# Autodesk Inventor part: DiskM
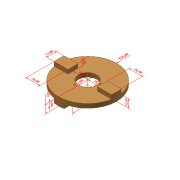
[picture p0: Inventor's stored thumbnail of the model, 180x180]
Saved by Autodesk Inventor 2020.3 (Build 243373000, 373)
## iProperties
Created: 2013-08
Part Number: DiskM
Document SubType Name: Modeling
Designer: hunter love
Density: 1 g/cm^3
Mass: 21.3803 g
Surface Area: 95.2224 cm^2
Volume: 21.3803 cm^3
Material: Generico
Appearance: Orange (Pale)
Author: hunter love
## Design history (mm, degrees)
node "Annotazioni"
  node "Quota radiale 1" dims "d9" = 90 deg, "d17" = 18, "d18" = 18, "d20" = 35 (derived)
  node "Quota diametro 1" dims "d9" = 90 deg, "d17" = 18, "d18" = 18, "d22" = 22 (derived)
  node "Quota lineare 1" dims "d9" = 90 deg, "d17" = 18, "d18" = 18, "d25" = 16.48188 (derived)
  node "Quota lineare 2" dims "d9" = 90 deg, "d17" = 18, "d18" = 18, "d28" = 12 (derived)
  node "Quota lineare 3" dims "d9" = 90 deg, "d17" = 18, "d18" = 18, "d31" = 16.48188 (derived)
  node "Quota lineare 4" dims "d9" = 90 deg, "d17" = 18, "d18" = 18, "d32" = 5 (derived)
  node "Quota lineare 5" dims "d9" = 90 deg, "d17" = 18, "d18" = 18, "d35" = 5 (derived)
  node "Quota lineare 7" dims "d9" = 90 deg, "d17" = 18, "d18" = 18, "d40" = 18 (derived)
  node "Quota lineare 8" dims "d9" = 90 deg, "d17" = 18, "d18" = 18, "d41" = 10 (derived)
  node "Quota lineare 9" dims "d9" = 90 deg, "d17" = 18, "d18" = 18, "d42" = 10 (derived)
  node "Quota lineare 10" dims "d9" = 90 deg, "d17" = 18, "d18" = 18, "d45" = 18 (derived)
  node "Quota lineare 11" dims "d9" = 90 deg, "d17" = 18, "d18" = 18, "d48" = 18 (derived)
  node "Quota lineare 12" dims "d9" = 90 deg, "d17" = 18, "d18" = 18, "d51" = 36 (derived)
sketch "Sketch1"
  geometry: L1 (-6, -34.482)-(-6, -18); L2 (-6, -18)-(6, -18); L3 (6, -18)-(6, -34.482); L4 (6, 34.482)-(6, 18); L5 (6, 18)-(-6, 18); L6 (-6, 18)-(-6, 34.482); L7 (0, 0)-(30.757, 0) reference; L8 (0, 0)-(0, 25.868) reference; A1 r 30 centre (0, 0) between (6, -29.394) and (6, 29.394); A2 r 30 centre (0, 0) between (-6, 29.394) and (-6, -29.394); A3 r 35 centre (0, 0) between (-6, 34.482) and (-6, -34.482); A4 r 35 centre (0, 0) between (6, -34.482) and (6, 34.482)
  constraints: 16 end point, 8 point on circle, 4 centre point, 4 point on line, 1 coincident, 1 horizontal, 1 perpendicular, 1 vertical
  dimensions: "d17" = 18 distance from line of L5 A1.centre; "d18" = 18 distance from line of L2 A1.centre
extrude "Extrusion1" new body sketch "Sketch1" distance "d0" = 5; taper "d1" = 0 deg
sketch "Sketch3"
  geometry: L1 (-6, -18)-(-6, -34.482) reference; L2 (6, -18)-(-6, -18) reference; L3 (6, -34.482)-(6, -18) reference; L4 (6, 18)-(6, 34.482) reference; L5 (-6, 18)-(6, 18) reference; L6 (-6, 34.482)-(-6, 18) reference; A1 r 35 centre (0, 0) between (6, -34.482) and (6, 34.482) reference; A2 r 35 centre (0, 0) between (-6, -34.482) and (6, -34.482); A3 r 35 centre (0, 0) between (6, 34.482) and (-6, 34.482)
  constraints: 4 end point, 4 point on circle, 2 centre point, 1 coincident
extrude "Extrusion3" join sketch "Sketch3" distance "d5" = 10; taper "d6" = 0 deg
sketch "Sketch4"
  geometry: L1 (-6, 34.482)-(-6, 18) reference; L2 (6, 18)-(6, 34.482) reference; L3 (-6, 18)-(6, 18) reference; L4 (-6, 29.394)-(-6, 18); L5 (-6, 18)-(6, 18); L6 (6, 18)-(6, 29.394); L7 (-29.394, -6)-(-18, -6); L8 (-18, -6)-(-18, 6); L9 (-18, 6)-(-29.394, 6); L10 (0, 0)-(0, -30); L11 (29.394, -6)-(18, -6); L12 (18, 6)-(29.394, 6); L13 (18, -6)-(18, 6); L14 (-18, 6)-(-34.482, 6); L15 (-18, -6)-(-34.482, -6); L16 (18, 6)-(34.482, 6); L17 (18, -6)-(34.482, -6); A1 r 30 centre (0, 0) between (29.394, -6) and (29.394, 6); A2 r 30 centre (0, 0) between (-29.394, 6) and (-29.394, -6); A3 r 35 centre (0, 0) between (-6, 34.482) and (6, 34.482) reference; A4 r 35 centre (0, 0) between (-34.482, 6) and (-34.482, -6); A5 r 35 centre (0, 0) between (34.482, -6) and (34.482, 6)
  constraints: 30 end point, 12 point on circle, 4 centre point, 4 symmetric about line, 3 point on line, 2 coincident, 2 collinear, 2 perpendicular, 1 parallel, 8 other
  dimensions: "d9" = 90 deg dimension on L10.start L4.start L7.start
extrude "Extrusion4" join sketch "Sketch4" distance "d11" = 5; taper "d12" = 0 deg
sketch "Sketch5"
  geometry: C1 r 11 at (0, 0); A1 r 30 centre (0, 0) between (-29.394, -6) and (29.394, -6) reference
  constraints: 1 centre point, 1 coincident
  dimensions: "d13" = 22 diameter of C1
extrude "Extrusion5" cut sketch "Sketch5" extent not by distance; stored distance "d14" = 5; taper "d15" = 0 deg
node "Asse di lavoro1"
node "Solido1"
node "Corpi solidi"
node "Corpi di superficie"
other parameters: "d19" = 15.73577 (derived), "d21" = 15.79416 (derived), "d23" = 0 (derived), "d26" = 0 (derived), "d29" = 0 (derived), "d33" = 0 (derived), "d39" = -2.42286 (derived), "d43" = 7.1851 (derived), "d44" = 4.30237 (derived), "d46" = -4.2221 (derived), "d47" = 6.15354 (derived), "d49" = 5.562 (derived), "d50" = 6.53774 (derived)
